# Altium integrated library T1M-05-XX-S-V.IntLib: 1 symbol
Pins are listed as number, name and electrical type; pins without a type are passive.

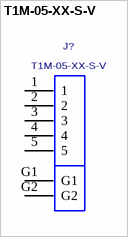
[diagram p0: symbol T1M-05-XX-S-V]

## T1M-05-XX-S-V
designator J?
1MM TERMINAL STRIP, 5 PINS.; MANUFACTURER: SAMTEC
footprint T1M-05-XX-S-V
pins: 1, 2, 3, 4, 5, G1, G2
